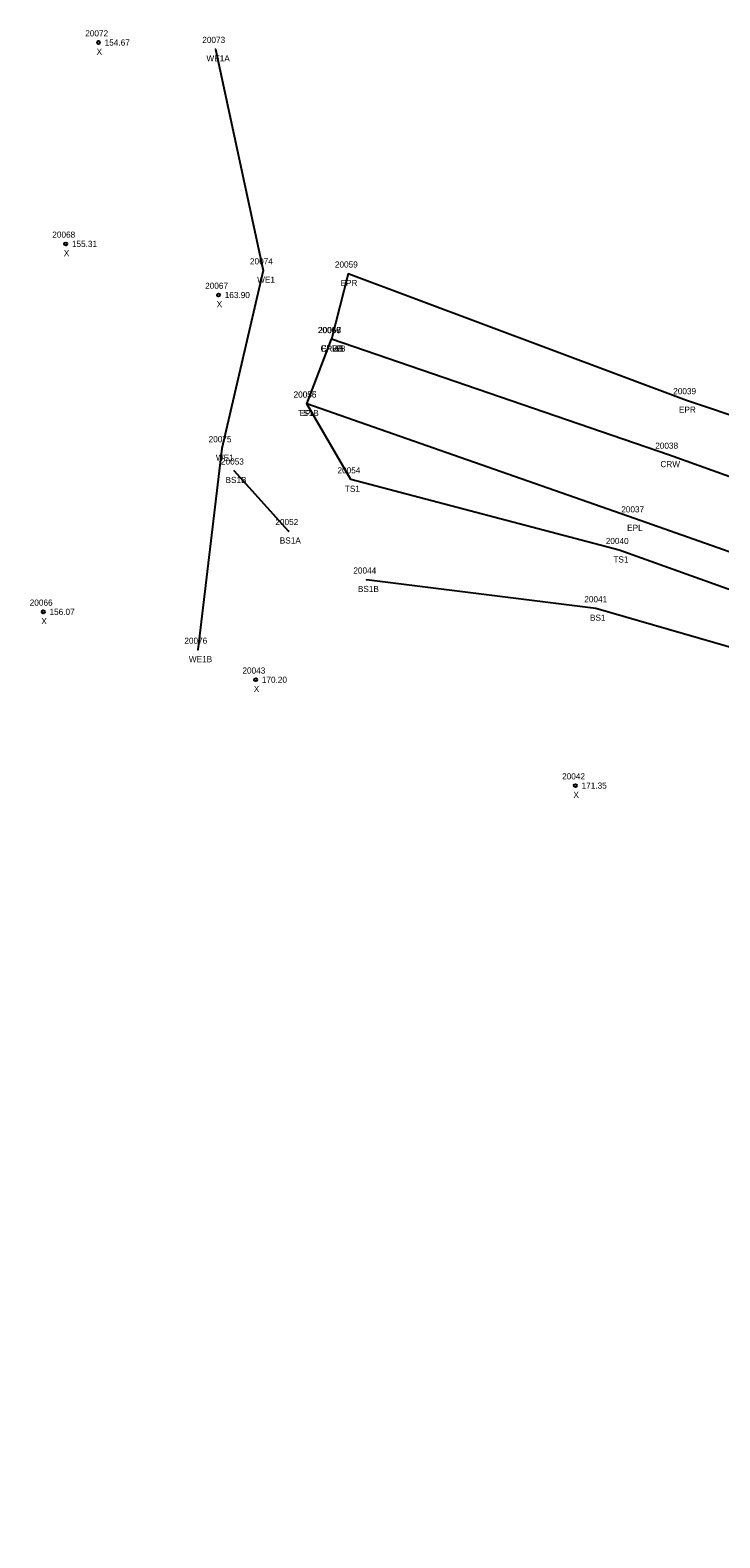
# Model space of a CAD drawing. Extents: x 2054705 to 2055845, y 756616 to 757058.
# Drawn here: x 2055287.1 to 2055399.2, y 756618.3 to 756863.4 of the extents above; entities that cross this region are included whole.
import ezdxf

# ---------------------------------------------------------------- set-up
doc = ezdxf.new("R2010")
doc.units = 0
for name, color, linetype in [('RD_DTM_BkLn1', 7, 'Continuous'), ('RD_DTM_BkLn2', 7, 'Continuous'), ('RD_EX_H2O', 7, 'Continuous'), ('RD_EX_H2O_txCode', 7, 'Continuous'), ('RD_EX_Road', 7, 'Continuous'), ('RD_EX_Road_txCode', 7, 'Continuous'), ('RD_Sketch8', 7, 'Continuous'), ('RD_SMD_Locator', 7, 'Continuous'), ('RD_SMD_Misc', 7, 'Continuous')]:
    doc.layers.add(name, color=color, linetype=linetype)

msp = doc.modelspace()

# ---------------------------------------------------------------- linework, layer by layer
at = {"layer": 'RD_DTM_BkLn1'}
msp.add_lwpolyline([(2055837.47, 756636.94), (2055735.89, 756672.36), (2055637.56, 756707.1), (2055542.66, 756740.62), (2055442.78, 756775.71), (2055390.81, 756794.36), (2055336.04, 756813.15)], dxfattribs=at)
at = {"layer": 'RD_DTM_BkLn2'}
msp.add_line((2055329.08, 756781.95), (2055320.24, 756791.79), dxfattribs=at)
for points in [[(2055832.49, 756621.52), (2055731.49, 756655.07), (2055631.3, 756688.56), (2055536.43, 756723.17), (2055435.45, 756760.01), (2055382.81, 756778.87), (2055339.17, 756790.36), (2055332.05, 756802.67)], [(2055831.8, 756618.33), (2055729.73, 756648.72), (2055627.89, 756676.46), (2055532.13, 756707.98), (2055433.53, 756753.65), (2055378.99, 756769.4), (2055341.75, 756774.07)]]:
    msp.add_lwpolyline(points, dxfattribs=at)
at = {"layer": 'RD_EX_H2O'}
msp.add_lwpolyline([(2055317.19, 756860.32), (2055324.95, 756824.33), (2055318.23, 756795.41), (2055314.32, 756762.66)], dxfattribs=at)
at = {"layer": 'RD_EX_Road'}
for points in [[(2055840.85, 756646.86), (2055741.4, 756681.66), (2055640.94, 756717.16), (2055546.09, 756750.42), (2055445.8, 756785.73), (2055393.73, 756803.22), (2055338.74, 756823.81), (2055336.04, 756813.15)], [(2055833.7, 756626.43), (2055733.14, 756661.47), (2055633.89, 756696.5), (2055538.99, 756729.94), (2055438.21, 756765.4), (2055385.28, 756784.01), (2055332.05, 756802.67), (2055336.04, 756813.15)]]:
    msp.add_lwpolyline(points, dxfattribs=at)
at = {"layer": 'RD_SMD_Locator'}
for centre, radius in [((2055298.18, 756861.39), 0.25), ((2055317.19, 756860.32), 0.001), ((2055292.85, 756828.66), 0.25), ((2055324.95, 756824.33), 0.001), ((2055338.74, 756823.81), 0.001), ((2055317.69, 756820.35), 0.25), ((2055336.04, 756813.15), 0.001), ((2055336.04, 756813.15), 0.001), ((2055336.04, 756813.15), 0.001), ((2055332.05, 756802.67), 0.001), ((2055332.05, 756802.67), 0.001), ((2055393.73, 756803.22), 0.001), ((2055318.23, 756795.41), 0.001), ((2055390.81, 756794.36), 0.001), ((2055320.24, 756791.79), 0.001), ((2055339.17, 756790.36), 0.001), ((2055385.28, 756784.01), 0.001), ((2055329.08, 756781.95), 0.001), ((2055382.81, 756778.87), 0.001), ((2055341.75, 756774.07), 0.001), ((2055289.21, 756768.85), 0.25), ((2055378.99, 756769.4), 0.001), ((2055314.32, 756762.66), 0.001), ((2055323.72, 756757.81), 0.25), ((2055375.68, 756740.61), 0.25)]:
    msp.add_circle(centre, radius, dxfattribs=at)

# ---------------------------------------------------------------- texts
at = {"layer": 'RD_EX_H2O_txCode'}
for s, p in [('20073', (2055315.04, 756861.32)), ('WE1A', (2055315.72, 756858.32)), ('20074', (2055322.79, 756825.33)), ('WE1', (2055323.96, 756822.33)), ('20075', (2055316.07, 756796.41)), ('WE1', (2055317.25, 756793.41)), ('20076', (2055312.13, 756763.66)), ('WE1B', (2055312.86, 756760.66))]:
    msp.add_text(s, height=1, dxfattribs=at).set_placement(p)
at = {"layer": 'RD_EX_Road_txCode'}
for s, p in [('20059', (2055336.59, 756824.81)), ('EPR', (2055337.51, 756821.81)), ('20060', (2055333.82, 756814.15)), ('20057', (2055333.88, 756814.15)), ('EPRB', (2055334.34, 756811.15)), ('EPLB', (2055334.36, 756811.15)), ('20056', (2055329.87, 756803.67)), ('20039', (2055391.57, 756804.22)), ('EPR', (2055392.5, 756801.22)), ('EPL', (2055330.85, 756800.67)), ('20037', (2055383.13, 756785.01)), ('EPL', (2055384.08, 756782.01))]:
    msp.add_text(s, height=1, dxfattribs=at).set_placement(p)
at = {"layer": 'RD_Sketch8'}
for s, p in [('20072', (2055296.02, 756862.39)), ('154.67', (2055299.18, 756860.89)), ('X', (2055297.87, 756859.39)), ('20068', (2055290.67, 756829.66)), ('155.31', (2055293.85, 756828.16)), ('X', (2055292.54, 756826.66)), ('20067', (2055315.51, 756821.35)), ('X', (2055317.38, 756818.35)), ('163.90', (2055318.69, 756819.85)), ('20066', (2055287, 756769.85)), ('X', (2055288.89, 756766.85)), ('156.07', (2055290.21, 756768.35)), ('20043', (2055321.57, 756758.81)), ('170.20', (2055324.72, 756757.31)), ('X', (2055323.41, 756755.81)), ('20042', (2055373.52, 756741.61)), ('171.35', (2055376.68, 756740.11)), ('X', (2055375.36, 756738.61))]:
    msp.add_text(s, height=1, dxfattribs=at).set_placement(p)
at = {"layer": 'RD_SMD_Misc'}
for s, p in [('20058', (2055333.88, 756814.15)), ('CRWB', (2055334.25, 756811.15)), ('20055', (2055329.89, 756803.67)), ('TS1B', (2055330.62, 756800.67)), ('20038', (2055388.65, 756795.36)), ('20053', (2055318.08, 756792.79)), ('20054', (2055337.02, 756791.36)), ('CRW', (2055389.49, 756792.36)), ('BS1B', (2055318.82, 756789.79)), ('TS1', (2055338.21, 756788.36)), ('20052', (2055326.92, 756782.95)), ('BS1A', (2055327.64, 756779.95)), ('20040', (2055380.61, 756779.87)), ('TS1', (2055381.85, 756776.87)), ('20044', (2055339.59, 756775.07)), ('BS1B', (2055340.33, 756772.07)), ('20041', (2055377.12, 756770.4)), ('BS1', (2055378.05, 756767.4))]:
    msp.add_text(s, height=1, dxfattribs=at).set_placement(p)

doc.saveas('drawing.dxf')
